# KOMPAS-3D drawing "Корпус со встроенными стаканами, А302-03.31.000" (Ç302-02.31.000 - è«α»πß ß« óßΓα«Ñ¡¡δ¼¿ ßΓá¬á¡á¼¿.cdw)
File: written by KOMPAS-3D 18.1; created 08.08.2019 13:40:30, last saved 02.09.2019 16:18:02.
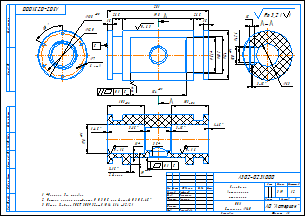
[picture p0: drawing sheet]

Sheet 1: A3, landscape

Document properties: Автор: Пользователь Windows; Параметр неуказанной шероховатости: Ra 3,2; Масса: 3.18846; Полное имя файла: ..\3Д ПВХ\А302-01.31.000 - Корпус со встроенными стаканами.m3d

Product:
- Part/product: Корпус со встроенными стаканами  | designation А302-03.31.000  | pos. 2
    Материал: Поливинилхлорид (density 1350 kg/m3)
    Масса: 2.81693
    source file: ..\..\А302-03.00.000 - ASTRA-302 (МЭ200)\А302-03.31.000 - Корпус со встроенными стаканами.cdw, ..\Чертежи Полипропилен\А302-03.31.000 - Корпус со встроенными стаканами.cdw
  - Body: Тело 19
      Масса: 3.54993
  - Body: Тело 18
      Масса: 3.54993
  - Body: (unnamed)
      Масса: 3.54993
- Part/product: Корпус со встроенными стаканами  | designation А302-01.31.000
    Материал: Поливинилхлорид (density 1350 kg/m3)
    Масса: 2.63451
- Part/product: Корпус со встроенными стаканами  | designation А302-02.31.000  | pos. 2
    Материал: Поливинилхлорид (density 1350 kg/m3)
    Масса: 3.18846
    source file: ..\3Д ПВХ\А302-02.00.000 - ASTRA-302 (МЭ200)\А302-02.31.000 - Корпус со встроенными стаканами.cdw, А302-02.31.000 - Корпус со встроенными стаканами.cdw
  - Body: (unnamed)
      Масса: 3.54993
  - Body: Тело 19
      Масса: 3.54993
  - Body: Тело 18
      Масса: 3.54993

Title block, sheet 1: Наименование: Корпус со / встроенными / стаканами; designation: А302-02.31.000; Материал: ПВХ / Стержень  140; Масса: 3,19; Количество листов документа: 1; organisation: АО "Астерион"; Форматы листов документа: A3; stored path: D:\Мембранные насосы\Мембранный электропривод\А302-00.00.000 - ASTRA-302 (МЭ200)\3Д ПВХ\А302-02.00.000 - ASTRA-302 (МЭ200)\А302-02.31.000 - Корпус со встроенными стаканами.cdw; Разработал: Лифлянд; Проверил: Борисенко; Т. контр.: Лучихин; Утвердил: Григорбева

Views: Проекционный вид 2, Проекционный вид 3, Разрез А-А, Проекционный вид 8, Местный разрез 1
Referenced files in D:\Мембранные насосы\Мембранный электропривод\А302-00.00.000 - ASTRA-302 (МЭ200)\3Д ПВХ\: А302-01.31.000 - Корпус со встроенными стаканами.m3d
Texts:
  Ra 6,3
  Ra 1,6
  Ra 3,2
  Ra 3,2 ( )
Dimensions and other numbers on the sheet: 138; 120; 7; 6 отв.; 3; 2 фаски; 281; 134; 102; 15; 26,5; 198; 154; 95,1; 42,6; 0,1; 50; 63; 103; 1; 78; 19; 3,5; 11; 1:2; 3,19

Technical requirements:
  *Размеры для справок.
  Острые кромки притупить R 0,3...0,5 или фаской 0,3...0,5х45 .
  Общие допуски ГОСТ 30893.2-mK (H14, h14,  t2/2).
